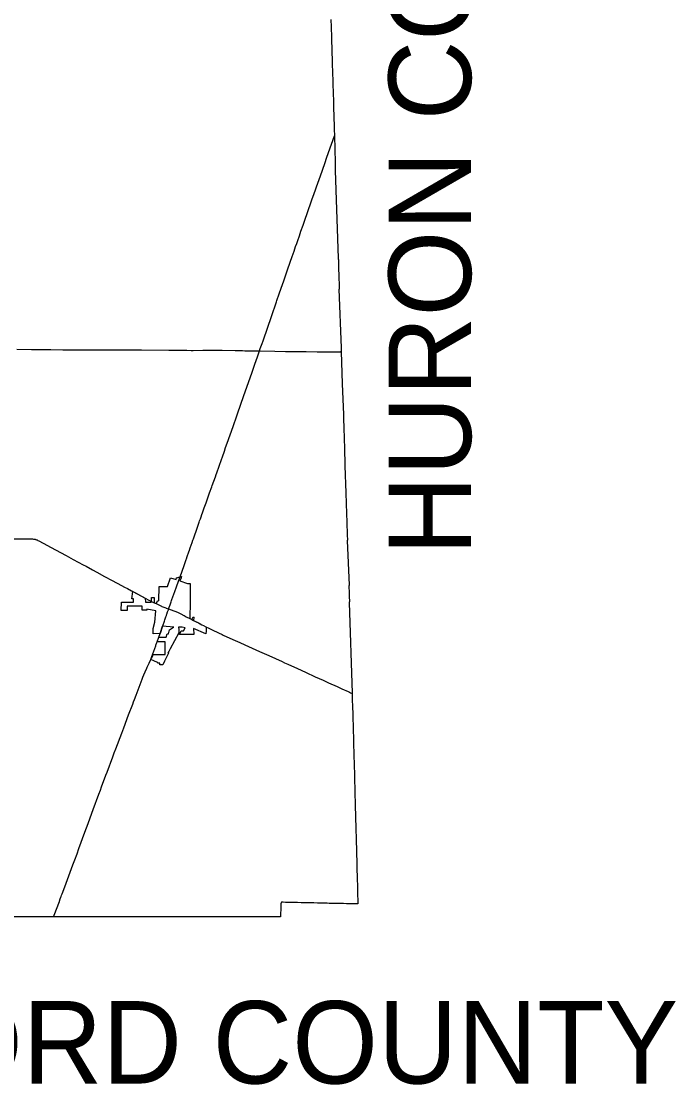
# Model space of a CAD drawing. Extents: x -786946 to -767280, y 417139 to 426807.
# Drawn here: x -769333 to -767473, y 417139 to 420161 of the extents above; entities that cross this region are included whole.
import ezdxf

# ---------------------------------------------------------------- set-up
doc = ezdxf.new("R2010")
doc.units = 0
for name, color, linetype in [('DV_X_Corp_Line', 7, 'Continuous'), ('DV_X_County_Line', 7, 'Continuous'), ('GM_X_State_Route', 7, 'Continuous'), ('SH_Text', 7, 'Continuous')]:
    doc.layers.add(name, color=color, linetype=linetype)

msp = doc.modelspace()

# ---------------------------------------------------------------- linework, layer by layer
at = {"layer": 'DV_X_Corp_Line'}
msp.add_lwpolyline([(-768899.5, 418439.6), (-768931.6, 418441.9), (-768939, 418420.8), (-768958.6, 418420.6), (-768958.5, 418435.8), (-768954.1, 418453.2), (-768951, 418486), (-768976.3, 418490.2), (-768976.2, 418487.5), (-768990.2, 418487.6), (-768990.1, 418499.2), (-769032.2, 418499), (-769032.5, 418486.4), (-769049.1, 418486.8), (-769048.4, 418510.5), (-769014.8, 418510.3), (-769014.9, 418517.3), (-769014.9, 418520), (-769019.6, 418519.9), (-769016.6, 418540.8), (-769004.4, 418534.2), (-768980.9, 418521.6), (-768980.3, 418510.5), (-768968.6, 418510.6), (-768964, 418510.7), (-768963.2, 418512.2), (-768963.2, 418523.5), (-768955.3, 418523.3), (-768955.5, 418508.6), (-768950.4, 418506.2), (-768945.2, 418515.4), (-768942.1, 418514.4), (-768941.9, 418555.2), (-768917.5, 418555.2), (-768909.3, 418579.8), (-768893.5, 418574.5), (-768891.8, 418579.3), (-768882.2, 418582.5), (-768877.7, 418583.5), (-768880.1, 418576.7), (-768880.2, 418576.7), (-768882.4, 418570.8), (-768882.5, 418570.5), (-768860.5, 418563.3), (-768853.2, 418563.3), (-768853.2, 418510.8), (-768853.9, 418463.5), (-768848.7, 418460.9), (-768844.9, 418468.4), (-768842.5, 418467.3), (-768843.9, 418458.5), (-768842.1, 418457.6), (-768834.8, 418453.8), (-768829.5, 418451.1), (-768826.3, 418449.5), (-768819.8, 418446.1), (-768815.5, 418443.9), (-768808.7, 418440.6), (-768808.3, 418439.9), (-768808.3, 418428.3), (-768809, 418420), (-768843.7, 418435.3), (-768843.4, 418418.6), (-768884.1, 418418.5), (-768878.8, 418429), (-768872.6, 418428.9), (-768868, 418437.7), (-768876, 418439.4), (-768886.1, 418439.6), (-768886, 418432.9), (-768885.9, 418422.8), (-768910.1, 418377.5), (-768913.9, 418370.5), (-768916.7, 418365.3), (-768914.9, 418365.4), (-768925.6, 418344.1), (-768926.2, 418342.8), (-768931.4, 418332.5), (-768931.4, 418332.5), (-768939.5, 418332.4), (-768939.5, 418336.9), (-768945.1, 418336.9), (-768945.1, 418337.9), (-768945.1, 418338.8), (-768946.1, 418339.2), (-768957.1, 418344), (-768965.5, 418347.7), (-768963.2, 418352.7), (-768962, 418352.2), (-768959.7, 418357.4), (-768958.4, 418361.7), (-768946.8, 418361.8), (-768932.1, 418361.9), (-768924.7, 418361.9), (-768924.7, 418381.6), (-768924.7, 418398), (-768942.4, 418397.7), (-768947.1, 418397.7), (-768942.5, 418410.9), (-768928.4, 418411), (-768921.7, 418411.1), (-768918.4, 418420.2), (-768915.4, 418420.1), (-768911.7, 418431.9), (-768903.9, 418437)], close=True, dxfattribs=at)
at = {"layer": 'DV_X_County_Line'}
msp.add_lwpolyline([(-768453.4, 420165.4), (-768452.8, 420144.8), (-768451.9, 420114.9), (-768451.5, 420101.6), (-768451, 420087.2), (-768450.8, 420078.8), (-768450.4, 420066.6), (-768450.1, 420057.8), (-768449.9, 420049.4), (-768449.5, 420037.8), (-768449.3, 420030.9), (-768449.1, 420023.9), (-768448.7, 420012.3), (-768448.1, 419993.4), (-768447.7, 419982.9), (-768447.4, 419971.8), (-768447.2, 419967.4), (-768447.1, 419962.4), (-768446.8, 419950.7), (-768446.4, 419939.1), (-768446.2, 419931.3), (-768446.1, 419925.2), (-768445.7, 419915.6), (-768445.5, 419909.1), (-768445.2, 419896.9), (-768444.6, 419878.6), (-768444.4, 419872), (-768444, 419859.8), (-768443.7, 419850.9), (-768443.7, 419850.6), (-768443.4, 419839.3), (-768443.5, 419835.3), (-768441.4, 419759.1), (-768441.1, 419736.7), (-768433.1, 419487.3), (-768432.9, 419487), (-768432.7, 419486.8), (-768432.5, 419486.2), (-768432.4, 419485.7), (-768432.3, 419485.1), (-768432.2, 419484), (-768432.1, 419478.5), (-768431.9, 419466.9), (-768431.7, 419461), (-768431.3, 419451), (-768431.1, 419445.5), (-768430.9, 419437.7), (-768430.6, 419426), (-768430.3, 419418.2), (-768430.1, 419411.6), (-768429.9, 419405.5), (-768429.8, 419402.1), (-768429.8, 419401), (-768429.9, 419400.5), (-768429.9, 419400.5), (-768430.1, 419400), (-768430.5, 419399.4), (-768423.9, 419232.8), (-768424.3, 419222.5), (-768421.2, 419130.5), (-768417.9, 419043.3), (-768417.8, 419043.1), (-768417.7, 419039.6), (-768417.3, 419025.7), (-768417.1, 419021.3), (-768417, 419015.2), (-768416.9, 419010.2), (-768416.7, 419005.8), (-768416.5, 419000.2), (-768416.2, 418992.5), (-768416.1, 418988.6), (-768415.9, 418981.4), (-768415.7, 418975.9), (-768415.5, 418969.2), (-768415.3, 418963.1), (-768415.1, 418958.7), (-768415, 418954.3), (-768414.8, 418947.1), (-768414.6, 418939.3), (-768414.4, 418930.4), (-768414.3, 418926.6), (-768414.1, 418920.5), (-768413.9, 418912.7), (-768413.8, 418907.7), (-768413.6, 418900.5), (-768413.3, 418890.5), (-768412.9, 418879.4), (-768412.8, 418874.5), (-768412.6, 418868.9), (-768412.5, 418866.1), (-768412.4, 418862.8), (-768412.2, 418855.1), (-768411.8, 418845.6), (-768411.6, 418837.9), (-768411.3, 418829), (-768411, 418822.9), (-768410.8, 418817.4), (-768410.7, 418811.3), (-768410.3, 418800.2), (-768410.1, 418793.6), (-768409.7, 418783), (-768409.5, 418778.6), (-768409.4, 418774.7), (-768409.3, 418771.4), (-768409.1, 418765.9), (-768409, 418762.6), (-768408.9, 418759.2), (-768408.7, 418753.7), (-768408.4, 418746.5), (-768408.2, 418738.2), (-768408.1, 418732.6), (-768407.9, 418727.1), (-768407.8, 418726.1), (-768407.7, 418722.7), (-768407.5, 418716.6), (-768407.3, 418712.2), (-768407.2, 418706.1), (-768406.9, 418698.3), (-768406.5, 418688.9), (-768406.5, 418686.7), (-768406.5, 418686.2), (-768406.7, 418685.7), (-768406.7, 418685.5), (-768401.5, 418558.5), (-768401.7, 418557.7), (-768401.9, 418556.9), (-768401.9, 418556.1), (-768402, 418553.9), (-768401.5, 418539), (-768401.2, 418525.3), (-768400.8, 418513.1), (-768400.8, 418512.8), (-768400.8, 418512.3), (-768400.8, 418511.9), (-768400.9, 418511.5), (-768401, 418511), (-768401.1, 418510.7), (-768401.3, 418510.2), (-768401.7, 418509.4), (-768392.8, 418251.6), (-768392.9, 418248.5), (-768392.5, 418235.8), (-768391.7, 418211.4), (-768391.2, 418194.8), (-768390.7, 418176.5), (-768390.3, 418162.2), (-768390, 418151.1), (-768389.1, 418119), (-768388.8, 418106.8), (-768388.7, 418098.5), (-768388.4, 418088.5), (-768387.7, 418064.7), (-768387.6, 418059.7), (-768387.2, 418044.8), (-768386.7, 418023.7), (-768386.2, 418004.4), (-768385.6, 417979.5), (-768385, 417959.5), (-768384.6, 417945.9), (-768384.4, 417941.8), (-768384.1, 417930.2), (-768383.9, 417921.3), (-768383.7, 417913), (-768383.3, 417894.8), (-768382.7, 417873.1), (-768381.5, 417831.1), (-768381.4, 417829.2), (-768380.8, 417809.5), (-768380.6, 417797.9), (-768380.4, 417793), (-768380.3, 417788.5), (-768380.1, 417780.2), (-768379.6, 417763.6), (-768379.4, 417753.2), (-768378.8, 417727.7), (-768378, 417699.5), (-768377.4, 417677.3), (-768377.1, 417665.2), (-768376.7, 417652.8), (-768379.4, 417652.8), (-768389.3, 417653.1), (-768399.8, 417653.3), (-768409.1, 417653.5), (-768417.9, 417653.7), (-768426.4, 417653.9), (-768432.8, 417654.1), (-768447.7, 417654.4), (-768456, 417654.6), (-768457.8, 417654.6), (-768458.2, 417654.6), (-768464.3, 417654.8), (-768475.8, 417655), (-768481.3, 417655.1), (-768491.3, 417655.4), (-768502.3, 417655.7), (-768507.8, 417655.8), (-768511.7, 417655.9), (-768515.5, 417655.9), (-768530.4, 417656.3), (-768538.1, 417656.4), (-768548.6, 417656.6), (-768555.8, 417656.8), (-768564, 417657), (-768576.7, 417657.3), (-768582.2, 417657.4), (-768588.8, 417657.5), (-768591.6, 417657.6), (-768592.7, 417657.6), (-768593.9, 417657.5), (-768594.5, 417656.2), (-768594.9, 417655.2), (-768595.3, 417654.1), (-768595.6, 417653.1), (-768595.8, 417651.4), (-768596, 417649.8), (-768596, 417648.4), (-768596.1, 417647), (-768596.1, 417637), (-768596.2, 417625.9), (-768596.3, 417616.4), (-768606.7, 417616.4), (-768616, 417616.4), (-768631.5, 417616.5), (-768642, 417616.5), (-768653.5, 417616.5), (-768663.5, 417616.4), (-768673.9, 417616.5), (-768681.3, 417616.5), (-768683.3, 417616.5), (-768687.7, 417616.5), (-768699.3, 417616.5), (-768715.8, 417616.6), (-768727.4, 417616.5), (-768744, 417616.5), (-768758.8, 417616.5), (-768768.8, 417616.5), (-768776.5, 417616.5), (-768785.1, 417616.5), (-768790.3, 417616.5), (-768810.1, 417616.6), (-768819.5, 417616.6), (-768829.4, 417616.7), (-768836.6, 417616.7), (-768854.2, 417616.7), (-768860.4, 417616.7), (-768863, 417616.7), (-768865.8, 417616.7), (-768878.5, 417616.7), (-768897.2, 417616.6), (-768925.9, 417616.6), (-768945.7, 417616.5), (-768959, 417616.5), (-768962.3, 417616.5), (-768971.7, 417616.5), (-768980.5, 417616.5), (-768999.8, 417616.5), (-769008.1, 417616.4), (-769020.7, 417616.4), (-769039.2, 417616.3), (-769040, 417616.3), (-769041.5, 417616.3), (-769051.1, 417616.3), (-769072.6, 417616.3), (-769075.4, 417616.3), (-769084.7, 417616.3), (-769098.5, 417616.3), (-769107.9, 417616.3), (-769128.8, 417616.2), (-769186.1, 417616.1), (-769196.6, 417616.1), (-769203.2, 417616), (-769209.8, 417616), (-769230.2, 417616), (-769241.6, 417616), (-769242.4, 417616), (-769247.9, 417616), (-769256.1, 417616), (-769315.1, 417616.2), (-769364.2, 417616.4)], dxfattribs=at)
at = {"layer": 'GM_X_State_Route'}
for p, q in [((-768477.6, 419737.7), (-768469.9, 419759.6)), ((-768886.6, 418569.9), (-768882.2, 418582.3)), ((-769016.6, 418540.8), (-769004.9, 418534.5)), ((-768848.7, 418460.9), (-768843.9, 418458.5)), ((-768939, 418420.8), (-768931.6, 418441.9)), ((-768947.2, 418397.6), (-768942.5, 418410.9)), ((-768942.5, 418410.9), (-768939, 418420.8))]:
    msp.add_line(p, q, dxfattribs=at)
for points in [[(-768469.9, 419759.6), (-768465.6, 419772), (-768460, 419788.1), (-768443.5, 419835.4)], [(-768501.7, 419668.8), (-768489.4, 419703.7), (-768487.9, 419708.1), (-768477.6, 419737.7)], [(-768779.7, 418872.7), (-768777.8, 418878.1), (-768764.4, 418915.8), (-768761.8, 418923.4), (-768756, 418939.7), (-768752.6, 418949.4), (-768748.3, 418961.6), (-768731.4, 419009.1), (-768720.5, 419040), (-768718.8, 419044.9), (-768700.5, 419097), (-768687.4, 419134.7), (-768677.3, 419163.7), (-768669.4, 419186.3), (-768662.1, 419207.4), (-768656.4, 419224.1), (-768654.1, 419230.6), (-768648.9, 419245.4), (-768646.3, 419253.2), (-768632.9, 419291.6), (-768623.6, 419318.7), (-768617.6, 419335.9), (-768613.1, 419349.1), (-768608, 419363.6), (-768606.7, 419367.4), (-768600.1, 419386.3), (-768594.5, 419402.4), (-768587.3, 419422.9), (-768575.5, 419456.9), (-768563.4, 419491.9), (-768558.1, 419507.1), (-768553.5, 419520.4), (-768550.5, 419529.1), (-768547.5, 419537.6), (-768542.8, 419551.5), (-768538.4, 419564.1), (-768532.4, 419581.1), (-768525.3, 419601.4), (-768521.5, 419612.1), (-768506.3, 419655.8), (-768501.7, 419668.8)], [(-769346.5, 419229), (-769304.6, 419228.3), (-769291.2, 419228.2), (-769272.1, 419228), (-769266.6, 419228), (-769256.8, 419227.9), (-769249.7, 419227.9), (-769215.3, 419227.5), (-769202.5, 419227.5), (-769181.7, 419227.3), (-769157, 419227.2), (-769107.1, 419227.3), (-769085.3, 419227.2), (-769031.3, 419227.3), (-769024.2, 419227.2), (-769010.3, 419227.1), (-768992.1, 419227), (-768914, 419226.3), (-768893.7, 419226), (-768873.6, 419225.9), (-768862.7, 419225.8), (-768850.5, 419225.7), (-768844.4, 419225.7), (-768817.3, 419225.8), (-768803.5, 419225.8), (-768784.7, 419225.8), (-768772.6, 419225.8), (-768762.3, 419225.8), (-768725.6, 419225.2), (-768704.7, 419224.9), (-768698.3, 419224.7), (-768669.8, 419224.3), (-768660.1, 419224.2), (-768656.4, 419224.1)], [(-768656.4, 419224.1), (-768612.6, 419223.4), (-768582.2, 419222.9), (-768543.1, 419222.4), (-768527.4, 419222.3), (-768523.3, 419222.2), (-768492.6, 419221.9), (-768486.6, 419221.9), (-768463.3, 419221.8), (-768440.5, 419221.9), (-768428.8, 419221.7), (-768426.8, 419221.8), (-768425.7, 419221.9), (-768425, 419222.1), (-768424.6, 419222.4), (-768424.3, 419222.6)], [(-768813.2, 418778), (-768808.2, 418792.2), (-768805.1, 418801.1), (-768798.2, 418820.5), (-768792.1, 418837.6), (-768790.5, 418842), (-768781.8, 418866.6), (-768779.7, 418872.7)], [(-768845.4, 418686.8), (-768844.1, 418690.4), (-768832.6, 418723.3), (-768831.6, 418726.2), (-768827.7, 418737.3), (-768826.4, 418740.9), (-768824.2, 418747), (-768822.2, 418752.6), (-768819.8, 418759.7), (-768818.1, 418764.3), (-768813.2, 418778)], [(-769385.3, 418690.3), (-769357.4, 418690.1), (-769315.1, 418690), (-769304.5, 418689.9), (-769301.6, 418689.8), (-769298.9, 418689.5), (-769296.6, 418689.2), (-769294.4, 418688.8), (-769293.2, 418688.5), (-769292.3, 418688.2), (-769290.3, 418687.6)], [(-769290.3, 418687.6), (-769288.6, 418686.9), (-769286.1, 418685.8), (-769283.3, 418684.4), (-769236.5, 418659.3), (-769206.2, 418643), (-769185.8, 418631.9), (-769157.5, 418616.6), (-769149.4, 418612.1), (-769130.9, 418602.1), (-769118.9, 418595.6), (-769096.4, 418583.4), (-769074.8, 418571.9), (-769048.3, 418557.8), (-769039.7, 418553.2), (-769031.4, 418548.8), (-769020, 418542.6)], [(-768882.2, 418582.3), (-768870.8, 418614.6), (-768865.8, 418628.8), (-768864.8, 418631.5), (-768864.1, 418633.3), (-768861.7, 418640.3), (-768857.2, 418653), (-768855.5, 418658.1), (-768853, 418665.1), (-768847.8, 418680.2), (-768845.4, 418686.8)], [(-768906, 418514.7), (-768905.1, 418517.5), (-768902.2, 418525.6), (-768896.9, 418540.5), (-768892.2, 418553.7), (-768886.6, 418569.9)], [(-769020, 418542.6), (-769019, 418542.1), (-769016.6, 418540.8)], [(-769004.9, 418534.5), (-769004.4, 418534.2), (-769000.4, 418532.1), (-768980.9, 418521.6)], [(-768980.9, 418521.6), (-768970.9, 418516.2), (-768966.2, 418513.7), (-768963.2, 418512.2)], [(-768963.2, 418512.2), (-768961.2, 418511.2), (-768955.5, 418508.6)], [(-768955.5, 418508.6), (-768950.4, 418506.2), (-768950.4, 418506.2)], [(-768950.4, 418506.2), (-768935.3, 418499.1), (-768934.9, 418498.9)], [(-768934.9, 418498.9), (-768933.5, 418498.2), (-768927.8, 418495.8), (-768923, 418494), (-768921.6, 418493.4), (-768921.5, 418493.4)], [(-768921.5, 418493.4), (-768914.5, 418490.9), (-768900, 418485.7), (-768899.7, 418485.6)], [(-768920.3, 418474.2), (-768919.6, 418476.4), (-768917.5, 418482.5), (-768915.3, 418488.8), (-768914.5, 418490.9), (-768910.2, 418502.8)], [(-768910.2, 418502.8), (-768909.4, 418505.2), (-768907.3, 418511.2), (-768906, 418514.7)], [(-768931.6, 418441.9), (-768931, 418443.4), (-768926.6, 418456), (-768925.1, 418460.3), (-768922.2, 418468.6), (-768921, 418472.1), (-768920.3, 418474.2)], [(-768899.7, 418485.6), (-768894.4, 418483.6), (-768892.5, 418482.9), (-768889.7, 418481.5), (-768885.8, 418479.5), (-768880.3, 418476.8), (-768871.1, 418472.2)], [(-768871.1, 418472.2), (-768870.6, 418472), (-768864.4, 418468.9), (-768853.9, 418463.5)], [(-768853.9, 418463.5), (-768853.9, 418463.5), (-768848.7, 418460.9)], [(-768843.9, 418458.5), (-768829.5, 418451.1), (-768819.8, 418446.1), (-768815.5, 418443.9), (-768808.7, 418440.6)], [(-768808.7, 418440.6), (-768800.4, 418436.4), (-768790.5, 418431.6), (-768772.6, 418423), (-768762.7, 418418.3), (-768759.2, 418416.7), (-768731.9, 418404.3), (-768712.5, 418395.6), (-768698.4, 418389.2), (-768656.6, 418370.5), (-768629.9, 418358.4), (-768592, 418341.4), (-768585, 418338.2), (-768575.5, 418333.8), (-768548.1, 418321.4), (-768525.4, 418311), (-768497.6, 418298.3), (-768475.4, 418288.2), (-768460.3, 418281.4), (-768435.9, 418270.4), (-768422.3, 418264.3), (-768404.5, 418256.1), (-768400.3, 418254.3), (-768397.3, 418253.1), (-768394.7, 418252.2), (-768392.9, 418251.7)], [(-768963.2, 418352.7), (-768962, 418355.9), (-768959.4, 418363.1), (-768951.2, 418386.3), (-768950.5, 418388.3), (-768948, 418395.5), (-768947.2, 418397.6)], [(-768976.9, 418322.4), (-768975.6, 418325.3), (-768970.2, 418337.4), (-768965.6, 418347.4)], [(-768965.6, 418347.4), (-768963.4, 418352.2), (-768963.2, 418352.7)], [(-769241.7, 417616.1), (-769239.8, 417621), (-769225.2, 417660.3), (-769224.9, 417661.2), (-769222.7, 417667.1), (-769220.8, 417672.2), (-769220.3, 417673.6), (-769218.9, 417677.4), (-769217.3, 417681.4), (-769209.7, 417701.9), (-769186.6, 417764.2), (-769181.3, 417778.4), (-769175, 417795.3), (-769169.7, 417810), (-769152.3, 417857.2), (-769148, 417869.3), (-769143.5, 417881.3), (-769137.5, 417897.7), (-769128.9, 417921), (-769112.8, 417964.7), (-769108.7, 417975.8), (-769105, 417985.6), (-769092.8, 418018.5), (-769089.4, 418027.6), (-769073.4, 418070.5), (-769069, 418081.9), (-769064.6, 418093.7), (-769047.7, 418138.5), (-769042.2, 418153.2), (-769028.3, 418189.9), (-769016.6, 418220.9), (-769014.3, 418227.3), (-769011.7, 418234.1), (-769007.1, 418246.4), (-769001.4, 418261.3), (-768989.8, 418291.6), (-768987.7, 418297.1), (-768984.8, 418304.1), (-768981.1, 418312.8), (-768976.9, 418322.4)]]:
    msp.add_lwpolyline(points, dxfattribs=at)

# ---------------------------------------------------------------- texts
at = {"layer": 'SH_Text'}
msp.add_text('HURON COUNTY', height=234.375, rotation=90, dxfattribs=at).set_placement((-768055, 418642.9))
msp.add_text('CRAWFORD COUNTY', height=234.375, dxfattribs=at).set_placement((-770722.1, 417142.6))

doc.saveas('drawing.dxf')
